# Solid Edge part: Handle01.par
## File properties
Author: ptcarter
Template: Normal.par
Last saved by: Ionut Lambrescu loco
Revision: 53
Application: Solid Edge
Accuracy: 0,99
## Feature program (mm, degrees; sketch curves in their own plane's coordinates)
sketch for "unnamed RevolvedProtrusion 1" plane through (0, 0, 0) normal (0, -1, 0) x-axis (1, 0, 0)
  line (-18, 12) -> (-18, 5)
  line (-18, 5) -> (0, 5)
  line (0, 5) -> (0, 0)
  line (0, 0) -> (-23, 0)
  arc centre (-15, 6) radius 10 from (-23, 12) to (-23, 0) ccw
  line (-18, 12) -> (-23, 12)
revolve "unnamed RevolvedProtrusion 1" add about sketch line (0, 10) -> (0, 35)
sketch for "unnamed Protrusion 1" plane through (110, 0, 0) normal (1, 0, 0) x-axis (0, 1, 0)
  line (-12, 9.5) -> (12, 9.5)
  line (12, 9.5) -> (12, 2.5)
  line (12, 2.5) -> (-12, 2.5)
  line (-12, 2.5) -> (-12, 9.5)
extrude "unnamed Protrusion 1" add
sketch for "unnamed Cutout 1" plane through (0, 0, 0) normal (0, 0, 1) x-axis (1, 0, 0)
  arc centre (0, 0) radius 7.5 from (-6.3443, 4) to (-6.3443, -4) ccw
  line (6.3443, -4) -> (-6.3443, -4)
  arc centre (0, 0) radius 7.5 from (6.3443, -4) to (6.3443, 4) ccw
  line (6.3443, 4) -> (-6.3443, 4)
extrude "unnamed Cutout 1" cut
fillet "Round_8" radius 12
fillet "Round_9" radius 3
fillet "Round_10" radius 3
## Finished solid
Body 1: solid body, 28 faces, 58 edges, 32 vertices.
  Faces by surface: plane 9, cylinder 8, blend 6, torus 5
  Edges by curve: circle 28, line 18, intersection 12
Bounding box of the edges (mm; curved faces can reach further): 133.000 x 46.000 x 12.000, from (-23, -23, 0) to (110, 23, 12).
Cylindrical faces by radius (mm): R3 x4, R7.5 x2, R12 x1, R18 x1
Toroidal faces (ring radius, tube radius in mm): R9 r3 x2, R15 r10 x1, R26.2583 r3 x2
Planar faces by outward normal: +y 2, +z 3, -y 2, -z 2
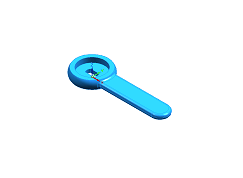
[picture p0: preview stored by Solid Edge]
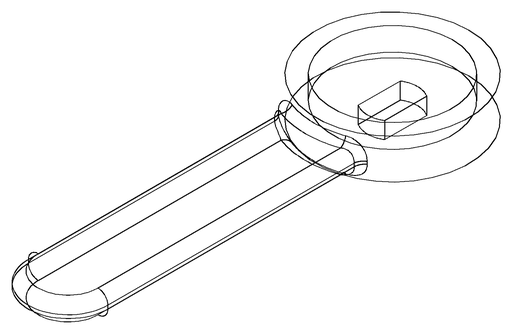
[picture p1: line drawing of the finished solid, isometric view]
